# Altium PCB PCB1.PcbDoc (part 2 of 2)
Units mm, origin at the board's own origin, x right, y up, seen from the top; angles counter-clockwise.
Board outline 100 x 72 mm, 4 copper layers (Top Layer, Ground, Power, Bottom Layer), stack 1.562 mm thick; 122 components, 105 nets, 454 pads, 324 vias.
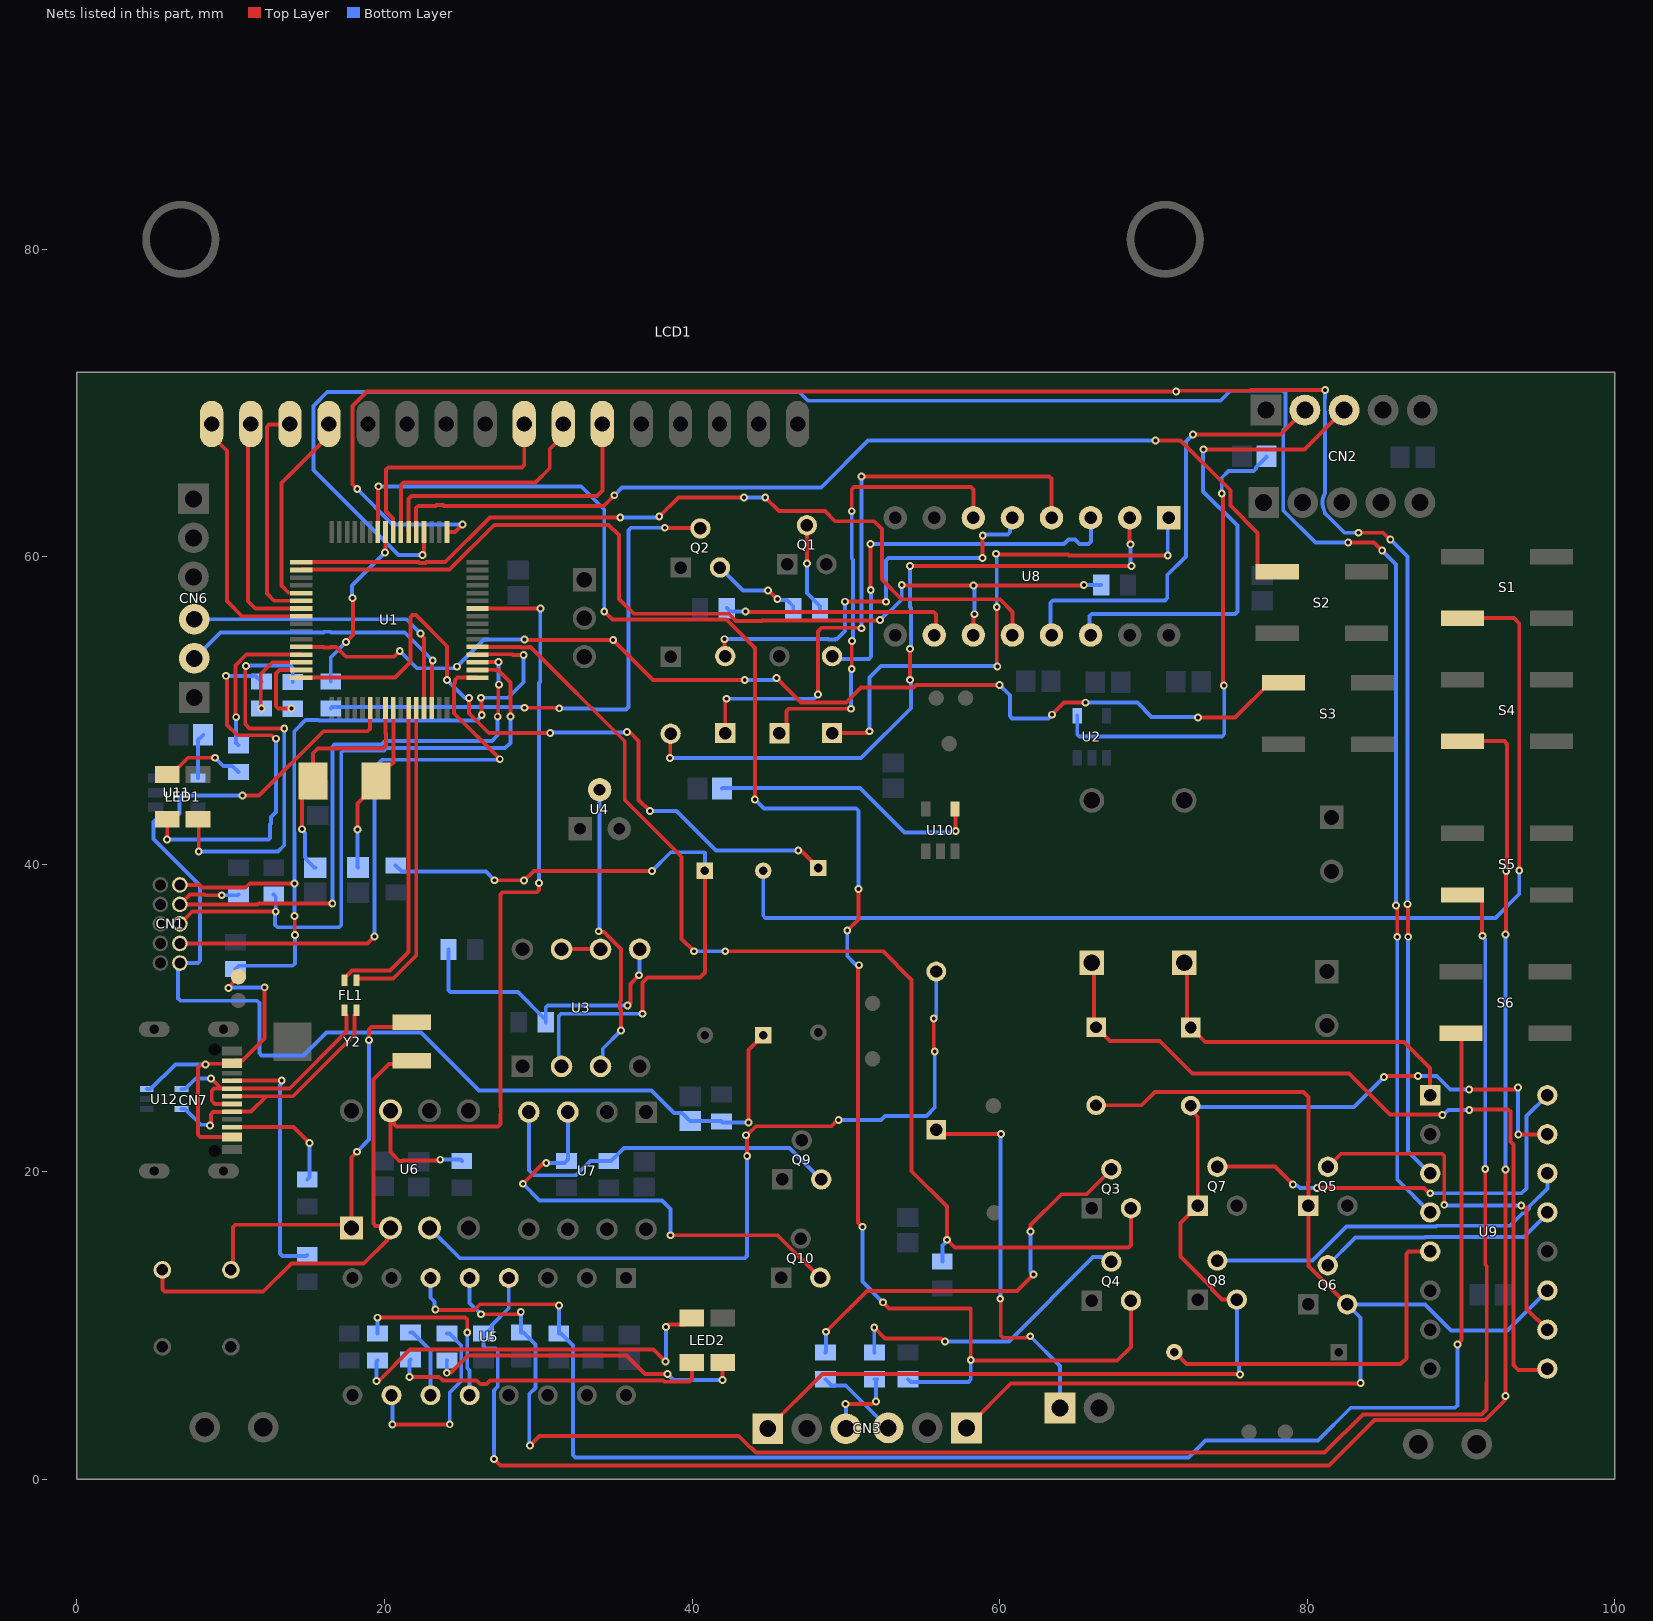
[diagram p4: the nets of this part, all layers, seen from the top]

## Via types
v1: diameter 0.508, hole 0.254, Top Layer to Bottom Layer, tented both sides, 324 vias

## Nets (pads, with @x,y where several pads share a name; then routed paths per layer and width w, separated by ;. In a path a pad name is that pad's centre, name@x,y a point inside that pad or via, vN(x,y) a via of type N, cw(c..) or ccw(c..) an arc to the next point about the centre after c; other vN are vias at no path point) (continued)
M0PWM0: U1.1 U9.3 | length 133.6
  Top Layer w0.254: v1(18.234,64.392) 17.92,64.705 17.92,69.797 18.861,70.738 v1(71.483,70.738) 71.53,70.786 76.297,70.786 76.355,70.843 v1(81.171,70.843) ; U1.1@24.07,61.605 24.591,61.605 v1(25.081,62.095) ; v1(83.339,61.551) 84.943,61.551 85.376,61.118 v1(85.408,61.118) ; v1(86.527,37.401) 86.568,37.36 v1(86.568,35.276)
  Bottom Layer w0.254: v1(18.234,64.392) 20.53,62.095 v1(25.081,62.095) ; v1(81.171,70.843) 81.144,69.559 ccw(c82.398,69.532) 81.171,69.273 81.171,64.151 ccw(c82.25,63.512) 81.075,63.072 81.171,62.817 81.239,62.749 82.437,61.551 v1(83.339,61.551) ; v1(85.408,61.118) 86.527,59.999 v1(86.527,37.401) ; v1(86.568,35.276) 86.568,21.329 U9.3@88,19.897
M0PWM1: U1.4 U9.4 | length 138.7
  Top Layer w0.254: v1(22.476,60.103) 22.476,60.171 22.57,60.265 U1.4@22.57,61.605 ; v1(82.668,60.918) 84.35,60.918 v1(84.878,60.39) ; v1(85.777,37.318) 85.86,37.235 v1(85.86,35.276)
  Bottom Layer w0.254: v1(22.476,60.103) 20.922,60.103 15.38,65.644 15.38,69.797 16.283,70.7 46.974,70.7 47.536,70.138 74.373,70.138 75.021,70.786 78.423,70.786 78.579,70.63 78.579,68.374 78.446,68.241 78.446,63.002 80.53,60.918 v1(82.668,60.918) ; v1(84.878,60.39) 85.777,59.491 v1(85.777,37.318) ; v1(85.86,35.276) 85.86,19.497 U9.4@88,17.357
MOTOR+: C14.2 CN3.1 Q5.1 Q6.3 U9.11 | length 76
  Top Layer w0.254: CN3.1@57.84,3.345 60.728,6.232 83.456,6.232 v1(83.479,6.255) ; C14.2@66.275,24.324 69.239,24.324 70.104,25.189 79.757,25.189 80.08,24.866 80.08,19.326 80.064,19.31 80.064,18.889 80.08,18.873 Q5.1@80.08,17.791 80.08,13.882 82.584,11.379 Q6.3@82.607,11.379
  Bottom Layer w0.254: v1(83.479,6.255) 83.479,10.507 Q6.3@82.607,11.379 87.651,11.379 89.355,9.675 93.018,9.675 U9.11@95.62,12.277
MOTOR-: C15.2 CN3.6 Q7.1 Q8.3 U9.15 | length 80
  Top Layer w0.254: CN3.6@44.926,3.297 48.483,6.854 75.597,6.854 v1(75.624,6.826) ; C15.2@72.424,24.3 72.424,24.025 72.888,23.562 Q7.1@72.888,17.791 71.772,16.675 71.772,14.481 73.802,12.451 73.802,12.35 74.466,11.685 Q8.3@75.428,11.685 ; v1(85,26.162) 85.119,26.162 85.19,26.233 v1(87.21,26.233) ; v1(90.535,25.354) 93.517,25.354 93.647,25.484 v1(93.715,25.484) ; v1(93.729,22.418) 93.739,22.428 95.611,22.428 U9.15@95.62,22.437
  Bottom Layer w0.254: C15.2@72.424,24.3 72.511,24.214 83.052,24.214 v1(85,26.162) ; Q8.3@75.428,11.685 75.428,7.588 75.576,7.44 75.576,6.875 v1(75.624,6.826) ; v1(87.21,26.233) 88.424,26.233 89.303,25.354 v1(90.535,25.354) ; v1(93.715,25.484) 93.722,25.477 93.722,22.425 v1(93.729,22.418)
NetB1_1: B1.1 D3.1 | length 24.9
  Top Layer w0.254: D3.1@55.88,22.733 56.155,22.458 v1(60.095,22.458) ; v1(60.044,11.742) 60.074,11.712 60.074,9.353 60.222,9.205 61.715,9.205 61.764,9.254 61.942,9.254 v1(61.991,9.303)
  Bottom Layer w0.254: v1(60.044,11.742) 60.07,11.767 60.07,22.432 v1(60.095,22.458) ; v1(61.991,9.303) 63.928,7.365 B1.1@63.928,4.646
NetC3_1: C3.1 CN1.10 R6.1 R7.1 U1.38 | length 82.2
  Top Layer w0.254: v1(10.779,44.468) 11.848,44.468 16.026,48.646 18.898,48.646 19.047,48.794 19.047,50.132 U1.38@19.07,50.155 ; v1(43.676,23.206) 43.676,27.924 R7.1@44.63,28.877
  Bottom Layer w0.254: v1(10.779,44.468) 6.813,44.468 6.665,44.319 6.665,43.296 6.516,43.148 5.382,43.148 4.98,42.746 4.98,41.644 8.015,38.609 8.015,33.724 7.866,33.575 CN1.10@6.702,33.575 6.585,33.458 6.585,31.27 6.734,31.121 11.717,31.121 11.866,30.972 11.866,27.72 12.014,27.571 14.739,27.571 16.232,29.064 22.366,29.064 26.151,25.279 37.366,25.279 38.82,23.825 39.356,23.825 C3.1@39.879,23.302 41.883,23.302 R6.1@41.914,23.272 41.98,23.206 v1(43.676,23.206)
NetC4_1: C4.1 U1.41 Y1.2 | length 11.4
  Top Layer w0.254: v1(18.247,42.26) 18.247,43.95 19.45,45.153 Y1.2@19.45,45.403 19.45,45.653 20.273,46.476 20.43,46.476 20.579,46.625 20.579,50.146 U1.41@20.57,50.155
  Bottom Layer w0.254: v1(18.247,42.26) 18.247,39.815 C4.1@18.276,39.786
NetC5_1: C5.1 U1.40 Y1.1 | length 15.5
  Top Layer w0.254: v1(14.64,42.277) 14.64,44.693 Y1.1@15.35,45.403 15.35,47.212 15.66,47.522 19.921,47.522 20.098,47.698 20.098,48.502 20.07,48.53 U1.40@20.07,50.155
  Bottom Layer w0.254: v1(14.64,42.277) 14.64,42.208 14.831,42.018 14.831,40.468 14.905,40.393 14.905,40.319 15.453,39.771 C5.1@15.503,39.771
NetC7_1: C7.1 U2.4 | length 31.2
  Top Layer w0.254: v1@74.496,64.103 74.538,64.061 74.538,51.654 v1(74.58,51.613)
  Bottom Layer w0.254: U2.4@65.05,49.661 65.05,48.444 65.199,48.295 74.457,48.295 74.61,48.448 74.61,51.582 v1(74.58,51.613) ; v1(74.448,64.103) 74.448,65.129 74.887,65.567 76.521,65.567 76.67,65.716 76.67,65.8 76.819,65.948 76.843,65.948 77.366,66.471 C7.1@77.366,66.521
NetC14_1: C14.1 D1.K U9.9 | length 52.8
  Top Layer w0.254: D1.K@66,33.598 66.144,33.454 66.144,29.535 67.172,28.508 70.412,28.508 72.528,26.392 82.726,26.392 85.395,23.722 88.759,23.722 v1(88.789,23.692) ; v1(90.539,24.008) 90.588,24.057 91.122,24.057 91.124,24.06 93.072,24.06 93.221,23.911 93.221,21.957 93.404,21.774 93.404,7.435 93.727,7.112 95.535,7.112 U9.9@95.62,7.197
  Bottom Layer w0.254: v1(88.789,23.692) 88.858,23.692 89.174,24.008 v1(90.539,24.008)
NetC15_1: C15.1 D2.K U9.1 | length 22.8
  Top Layer w0.254: D2.K@72,33.598 72.184,33.414 72.184,29.621 C15.1@72.424,29.38 73.373,28.431 86.307,28.431 88,26.739 U9.1@88,24.977
NetC18_1: C18.1 U10.4 | length 17.9
  Top Layer w0.254: U10.4@57.103,43.591 57.125,43.569 57.125,42.182 v1(57.146,42.161)
  Bottom Layer w0.254: C18.1@41.953,44.922 41.995,44.965 50.925,44.965 53.819,42.07 57.056,42.07 v1(57.146,42.161)
NetC21_1: C21.1 U8.1 | length 35.7
  Top Layer w0.254: C21.1@49.104,48.528 51.413,48.528 v1(51.532,48.647) ; v1(59.761,60.187) 59.81,60.139 59.989,60.139 60.003,60.125 64.457,60.125 64.509,60.074 v1(70.934,60.074) ; v1(59.812,56.718) 59.812,52.888 v1(59.851,52.849)
  Bottom Layer w0.254: v1(51.532,48.647) 51.532,52.138 52.282,52.888 59.799,52.888 59.838,52.849 v1(59.851,52.849) ; v1(59.761,60.187) 59.812,60.136 v1(59.812,56.718) ; v1(70.934,60.074) 70.934,62.459 U8.1@70.996,62.522
NetC21_2: C21.2 U8.3 | length 26.2
  Top Layer w0.254: v1(51.606,60.825) 51.613,60.817 51.613,57.829 v1(51.62,57.822)
  Bottom Layer w0.254: C21.2@49.104,53.528 49.292,53.34 51.501,53.34 51.65,53.489 51.65,57.793 v1(51.62,57.822) ; v1(51.606,60.825) 64.196,60.824 64.485,61.114 64.906,61.114 65.195,60.824 65.77,60.824 65.938,60.993 65.938,62.5 U8.3@65.916,62.522
NetC22_1: C22.1 U8.4 | length 40.2
  Top Layer w0.254: C22.1@42.158,48.528 42.158,50.685 v1(42.232,50.759) ; v1(48.186,51.027) 48.186,55.142 48.42,55.376 50.985,55.376 v1(51.02,55.342) ; v1(51.02,65.219) 63.215,65.219 63.363,65.07 63.363,62.535 U8.4@63.376,62.522
  Bottom Layer w0.254: v1(42.232,50.759) 47.918,50.759 v1(48.186,51.027) ; v1(51.02,55.342) v1(51.02,65.219)
NetC22_2: C22.2 U8.5 | length 27.2
  Top Layer w0.254: v1(42.103,54.631) 42.103,53.583 C22.2@42.158,53.528 ; v1(49.949,57.07) 52.604,57.07 v1(52.61,57.064) ; v1(58.885,59.906) 58.885,61.353 v1(58.904,61.372)
  Bottom Layer w0.254: v1(42.103,54.631) 48.849,54.631 48.876,54.605 49.297,54.605 49.323,54.631 49.428,54.631 49.949,55.152 v1(49.949,57.07) ; v1(52.61,57.064) 52.61,59.753 52.763,59.906 v1(58.885,59.906) ; v1(58.904,61.372) 58.973,61.372 59.036,61.435 60.517,61.435 60.666,61.584 60.666,62.351 U8.5@60.836,62.522
NetC23_2: C23.2 U8.2 | length 45.5
  Top Layer w0.254: v1(38.565,46.898) 38.585,46.918 38.585,48.465 C23.2@38.606,48.486 ; v1(54.166,54.005) 54.174,53.997 54.174,51.999 v1(54.182,51.99) ; v1(54.166,59.391) v1(68.568,59.391) ; U8.2@68.456,62.522 68.456,60.849 v1(68.506,60.8)
  Bottom Layer w0.254: v1(38.565,46.898) 50.988,46.898 54.228,50.138 54.228,51.944 v1(54.182,51.99) ; v1(54.166,54.005) 54.232,54.072 54.232,56.664 54.166,56.73 v1(54.166,59.391) ; v1(68.506,60.8) 68.506,59.453 v1(68.568,59.391)
NetC24_1: C24.1 U8.6 | length 30.1
  Top Layer w0.254: C24.1@45.683,48.51 46.138,48.965 46.138,49.957 46.286,50.106 v1(50.337,50.106) ; v1(50.383,52.7) 50.383,54.491 v1(50.399,54.506) ; v1(50.388,62.955) 50.388,64.366 50.536,64.515 58.148,64.515 58.296,64.366 U8.6@58.296,62.522
  Bottom Layer w0.254: v1(50.337,50.106) 50.337,52.653 v1(50.383,52.7) ; v1(50.388,62.955) 50.388,59.869 50.457,59.8 50.457,54.633 50.399,54.575 v1(50.399,54.506)
NetC26_1: C26.1 U11.4 | length 2.9
  Bottom Layer w0.254: U11.4@7.877,45.602 7.877,48.07 C26.1@8.215,48.409
NetC28_1: C28.1 U6.2 Y2.1 | length 31.8
  Top Layer w0.254: C28.1@5.56,13.617 5.56,12.35 5.709,12.202 12.117,12.202 13.944,14.029 18.656,14.029 20.153,15.525 20.153,16.107 U6.2@20.391,16.346 20.264,16.472 19.427,16.472 19.278,16.621 19.278,25.992 20.289,27.003 21.564,27.003 Y2.1@21.771,27.211
NetC29_1: C29.1 U6.1 Y2.2 | length 27
  Top Layer w0.254: C29.1@10.019,13.617 10.16,13.758 10.16,16.406 10.309,16.554 17.642,16.554 U6.1@17.851,16.346 17.851,20.946 v1(18.207,21.301) ; v1(18.99,28.556) 18.99,29.256 19.139,29.405 21.466,29.405 Y2.2@21.771,29.711
  Bottom Layer w0.254: v1(18.207,21.301) 18.99,22.085 v1(18.99,28.556)
NetCN1_2: CN1.2 R5.1 U1.52 | length 48.6
  Top Layer w0.254: CN1.2@6.702,38.655 7.972,38.655 8.144,38.483 9.208,38.483 9.212,38.486 10.982,38.486 11.242,38.746 v1(14.146,38.746) ; v1(14.146,36.629) 14.164,36.611 14.164,35.413 v1(14.183,35.394) ; U1.52@26.045,53.63 26.068,53.653 28.29,53.653 28.349,53.594 v1(29.052,53.594) ; v1(26.284,50.822) 26.305,50.801 26.305,49.728 v1(26.326,49.707)
  Bottom Layer w0.254: R5.1@10.318,33.175 10.538,33.395 14.034,33.395 14.183,33.544 v1(14.183,35.394) ; v1(14.146,36.629) v1(14.146,38.746) 14.146,42.053 14.132,42.066 14.132,48.627 14.878,49.372 15.703,49.372 15.729,49.346 26.024,49.346 26.326,49.648 v1(26.326,49.707) ; v1(26.284,50.822) 28.042,50.822 29.052,51.832 v1(29.052,53.594)
NetCN1_4: CN1.4 R4.2 U1.51 | length 41.5
  Top Layer w0.254: v1(9.422,37.978) 8.348,37.978 8.293,38.033 7.35,38.033 CN1.4@6.702,37.385 11.747,37.385 11.799,37.436 v1(16.609,37.436) ; U1.51@26.045,53.13 26.052,53.137 27.406,53.137 v1(27.413,53.145) ; v1(27.361,49.593) 27.401,49.633 27.401,51.632 v1(27.441,51.672)
  Bottom Layer w0.254: v1(9.422,37.978) 10.462,37.978 R4.2@10.502,38.018 ; v1(16.609,37.436) 16.609,47.635 16.758,47.784 19.801,47.784 20.026,48.01 26.987,48.01 27.361,48.384 v1(27.361,49.593) ; v1(27.413,53.145) 27.427,53.131 27.427,51.686 v1(27.441,51.672)
NetCN1_6: CN1.6 R3.2 U1.50 | length 41.9
  Top Layer w0.254: CN1.6@6.702,36.115 7.5,36.913 v1(12.932,36.913) ; U1.50@26.061,52.646 27.194,52.646 27.203,52.637 27.372,52.637 28.191,51.818 v1(28.191,49.6)
  Bottom Layer w0.254: R3.2@12.797,38.018 12.932,37.883 v1(12.932,36.913) ; v1@12.888,36.913 12.888,36.051 13.037,35.902 17.041,35.902 17.189,36.051 17.189,47.254 17.338,47.403 19.958,47.403 20.101,47.546 27.844,47.546 28.191,47.893 v1(28.191,49.6)
NetCN1_8: CN1.8 U1.49 | length 40.1
  Top Layer w0.254: CN1.8@6.702,34.845 18.91,34.845 v1(19.36,35.295) ; U1.49@26.045,52.13 24.733,52.13 24.585,51.981 24.585,51.767 24.534,51.717 24.534,49.816 27.502,46.848 v1(27.502,46.829)
  Bottom Layer w0.254: v1(19.36,35.295) 19.357,35.298 19.357,46.313 19.836,46.793 27.466,46.793 v1(27.502,46.829)
NetCN2_2: CN2.2 U8.13 | length 29.1
  Top Layer w0.254: v1(72.569,67.95) 78.276,67.95 CN2.2@79.858,69.532
  Bottom Layer w0.254: U8.13@63.376,54.902 63.305,54.973 63.305,57 63.454,57.149 70.755,57.149 70.904,57.298 70.904,58.797 72.118,60.011 72.118,67.498 v1(72.569,67.95)
NetCN2_3: CN2.3 U8.14 | length 32.7
  Top Layer w0.254: v1(73.249,66.976) 73.27,66.956 79.822,66.956 CN2.3@82.398,69.532
  Bottom Layer w0.254: U8.14@65.916,54.902 65.845,54.973 65.845,56.132 65.993,56.281 75.309,56.281 75.458,56.43 75.458,62.013 73.225,64.246 73.225,66.952 v1(73.249,66.976)
NetCN3_3: CN3.3 R22.1 | length 5.4
  Bottom Layer w0.254: R22.1@48.672,6.508 49.07,6.11 49.996,6.11 CN3.3@52.76,3.345
NetCN3_4: CN3.4 R23.1 | length 5.3
  Top Layer w0.254: v1(49.975,4.889) 51.721,4.889 51.89,5.059 v1(51.959,5.059)
  Bottom Layer w0.254: v1(49.975,4.889) 50.006,4.859 CN3.4@50.006,3.297 ; R23.1@51.872,6.508 52.022,6.508 51.959,6.445 v1(51.959,5.059)
NetCN7_A5: CN7.A5 R37.2 | length 16.4
  Top Layer w0.254: CN7.A5@10.092,25.907 10.115,25.93 10.736,25.93 10.738,25.931 13.32,25.931 v1(13.322,25.93)
  Bottom Layer w0.254: v1(13.322,25.93) 13.273,25.881 13.273,25.715 13.212,25.654 13.212,14.678 13.361,14.53 14.912,14.53 R37.2@14.979,14.597
NetCN7_B5: CN7.B5 R36.2 | length 7.9
  Top Layer w0.254: CN7.B5@10.092,22.907 14.076,22.907 v1(15.121,21.861)
  Bottom Layer w0.254: R36.2@14.979,19.499 15.121,19.641 v1(15.121,21.861)
NetD3_2: D3.2 U6.3 | length 51.4
  Top Layer w0.254: v1(43.586,21.028) 43.586,22.31 v1(43.516,22.38) 43.569,22.38 44.148,22.959 49.058,22.959 49.467,23.369 v1(49.536,23.369) ; v1(55.716,29.97) 55.716,27.89 v1(55.785,27.821)
  Bottom Layer w0.254: U6.3@22.931,16.346 24.903,14.374 43.437,14.374 43.586,14.522 v1(43.586,21.028) ; v1(49.536,23.369) 52.289,23.369 52.554,23.635 55.238,23.635 55.785,24.182 v1(55.785,27.821) ; v1(55.716,29.97) 55.88,30.134 D3.2@55.88,33.02
NetLCD1_4: LCD1.4 U1.6 | length 19.3
  Top Layer w0.254: U1.6@21.561,61.614 21.561,63.753 21.763,63.955 33.82,63.955 34.168,64.303 LCD1.4@34.168,68.626
NetLCD1_5: LCD1.5 U1.7 | length 16.4
  Top Layer w0.254: U1.7@21.072,61.607 21.072,64.665 21.221,64.814 29.817,64.814 30.75,65.746 30.75,66.993 31.628,67.872 LCD1.5@31.628,68.626
NetLCD1_6: LCD1.6 U1.8 | length 16
  Top Layer w0.254: U1.8@20.57,61.605 20.549,61.626 20.549,62.49 20.111,62.929 20.111,65.658 20.26,65.807 28.939,65.807 29.088,65.956 LCD1.6@29.088,68.626
NetLCD1_11: LCD1.11 U1.21 | length 13.3
  Top Layer w0.254: U1.21@14.595,57.63 14.572,57.653 13.755,57.653 13.299,58.109 13.299,64.783 16.388,67.872 LCD1.11@16.388,68.626
NetLCD1_12: LCD1.12 U1.22 | length 14.9
  Top Layer w0.254: LCD1.12@13.848,68.626 13.814,68.592 12.504,68.592 12.356,68.443 12.356,57.591 12.817,57.13 U1.22@14.595,57.13
NetLCD1_13: LCD1.13 U1.23 | length 15.3
  Top Layer w0.254: LCD1.13@11.308,68.626 11.131,68.449 11.131,57.099 11.6,56.63 U1.23@14.595,56.63
NetLCD1_14: LCD1.14 U1.24 | length 17.2
  Top Layer w0.254: LCD1.14@8.768,68.626 8.768,67.872 9.754,66.886 9.754,57.116 10.746,56.125 U1.24@14.59,56.125
NetLED1_1: LED1.1 R11.2 | length 5.5
  Top Layer w0.254: LED1.1@5.877,45.825 6.127,45.825 7.221,46.919 v1(8.98,46.919)
  Bottom Layer w0.254: v1(8.98,46.919) 9.515,46.385 10.104,46.385 R11.2@10.502,45.987
NetLED1_2: LED1.2 R34.2 | length 23.9
  Top Layer w0.254: v1(5.86,41.607) 5.877,41.624 LED1.2@5.877,42.925 ; v1(9.7,52.25) 9.749,52.201 9.749,52.021 9.761,52.01 9.761,49.058 10.435,48.384 12.666,48.384 12.887,48.163 v1(12.942,48.163)
  Bottom Layer w0.254: v1(5.86,41.607) 12.454,41.607 12.556,41.708 12.556,42.592 12.616,42.653 12.616,43.073 12.942,43.399 v1(12.942,48.163) ; v1(9.7,52.25) 11.625,52.25 R34.2@12,51.875
NetLED1_3: LED1.3 R33.2 | length 25.9
  Top Layer w0.254: LED1.3@7.877,42.925 7.924,42.878 v1(7.924,40.829) ; v1(10.989,52.888) 10.946,52.845 10.946,49.107 11.226,48.827 v1(13.485,48.827)
  Bottom Layer w0.254: v1(7.924,40.829) 13.081,40.829 13.486,41.235 13.486,48.826 v1(13.485,48.827) ; v1(10.989,52.888) 11.01,52.909 13.885,52.909 14.034,52.76 R33.2@14.034,51.854
NetLED2_1: LED2.1 R12.2 | length 25.5
  Top Layer w0.254: v1(19.481,6.403) 19.523,6.445 19.67,6.445 21.671,8.447 37.483,8.447 v1(38.267,7.662) ; v1(38.309,9.908) 38.465,10.064 39.564,10.064 LED2.1@39.987,10.487
  Bottom Layer w0.254: v1(19.481,6.403) 19.481,7.674 R12.2@19.541,7.734 ; v1(38.267,7.662) 38.309,7.704 v1(38.309,9.908)
NetLED2_2: LED2.2 R13.2 | length 21
  Top Layer w0.254: v1(21.62,6.653) 23.56,6.653 23.797,6.417 26.001,6.417 26.227,6.192 26.648,6.192 26.873,6.417 38.127,6.417 38.201,6.343 38.622,6.343 38.633,6.354 39.838,6.354 39.987,6.503 LED2.2@39.987,7.587
  Bottom Layer w0.254: v1(21.62,6.653) 21.62,7.735 R13.2@21.686,7.801
NetLED2_3: LED2.3 R14.2 | length 21
  Top Layer w0.254: v1(24.051,6.925) 24.1,6.974 24.35,6.974 25.42,8.043 35.737,8.043 36.929,6.851 v1(38.411,6.851) ; v1(41.984,6.466) 41.987,6.469 LED2.3@41.987,7.587
  Bottom Layer w0.254: v1(24.051,6.925) 24.051,7.72 R14.2@24.067,7.736 ; v1(38.411,6.851) 38.796,6.466 v1(41.984,6.466)
NetQ1_2: Q1.2 R9.2 | length 5.8
  Top Layer w0.254: Q1.2@47.47,62.045 47.473,62.041 47.473,59.551 v1(47.476,59.548)
  Bottom Layer w0.254: v1(47.476,59.548) 47.476,57.63 48.331,56.775 R9.2@48.331,56.625
NetQ2_2: Q2.2 R10.2 | length 35.8
  Top Layer w0.254: v1(29.111,50.174) 31.329,50.174 v1(31.367,50.136) ; v1(38.231,61.88) 38.255,61.856 40.523,61.856 Q2.2@40.546,61.832
  Bottom Layer w0.254: R10.2@16.509,50.125 16.599,50.215 29.069,50.215 v1(29.111,50.174) ; v1(31.367,50.136) 33.538,50.136 33.609,50.065 35.711,50.065 35.86,50.214 35.86,61.707 36.032,61.88 v1(38.231,61.88)
NetQ2_3: Q2.3 R9.1 | length 6
  Top Layer w0.254: v1(44.947,57.79) 44.975,57.79 45.518,57.246 v1(45.546,57.246)
  Bottom Layer w0.254: Q2.3@41.816,59.292 43.319,57.79 v1(44.947,57.79) ; v1(45.546,57.246) 45.615,57.246 45.688,57.173 46.183,57.173 46.581,56.775 R9.1@46.581,56.625
NetQ3_2: Q3.2 R22.2 | length 26.4
  Top Layer w0.254: v1(48.719,9.598) 51.371,12.25 61.135,12.25 v1(62.198,13.313) ; v1(62.007,16.108) 62.007,16.529 64.017,18.539 65.644,18.539 Q3.2@67.27,20.165
  Bottom Layer w0.254: R22.2@48.672,8.258 48.719,8.305 v1(48.719,9.598) ; v1(62.007,16.108) 62.007,13.504 v1(62.198,13.313)
NetQ4_2: Q4.2 R23.2 | length 19.8
  Top Layer w0.254: v1(51.851,9.872) 52.561,9.162 56.181,9.162 56.371,8.972 v1(56.44,8.972)
  Bottom Layer w0.254: v1(51.851,9.872) 51.851,8.278 R23.2@51.872,8.258 ; v1(56.44,8.972) 60.598,8.972 66.087,14.46 66.681,14.46 66.981,14.16 Q4.2@67.27,14.16
NetQ5_1: 
NetQ5_2: Q5.2 U9.10 | length 25.1
  Top Layer w0.254: Q5.2@81.35,20.331 82.188,21.169 88.768,21.169 88.917,21.02 v1(88.917,17.851) ; v1(93.922,17.812) 93.991,17.812 94.139,17.663 94.273,17.663 94.273,11.084 U9.10@95.62,9.737
  Bottom Layer w0.254: v1(88.917,17.851) 88.959,17.851 88.999,17.812 v1(93.922,17.812)
NetQ6_1: 
NetQ6_2: Q6.2 U9.13 | length 15.8
  Bottom Layer w0.254: Q6.2@81.337,13.919 83.149,15.731 87.668,15.731 87.691,15.754 94.095,15.754 95.62,17.28 U9.13@95.62,17.357
NetQ7_1: 
NetQ7_2: Q7.2 U9.16 | length 27.6
  Top Layer w0.254: Q7.2@74.158,20.331 77.903,20.331 v1(79.068,19.165) ; v1(80.634,18.937) 87.597,18.937 87.934,18.6 v1(88.002,18.6)
  Bottom Layer w0.254: v1(79.068,19.165) 79.117,19.116 79.357,19.116 79.536,18.937 v1(80.634,18.937) ; v1(88.002,18.6) 93.943,18.6 94.261,18.918 94.261,23.618 U9.16@95.62,24.977
NetQ8_1: 
NetQ8_2: Q8.2 U9.14 | length 24.5
  Bottom Layer w0.254: Q8.2@74.158,14.225 80.35,14.225 82.569,16.444 87.62,16.444 87.621,16.443 88.379,16.443 88.426,16.49 93.194,16.49 94.008,17.304 94.132,17.304 94.43,17.602 94.43,17.726 95.62,18.916 U9.14@95.62,19.897
NetQ9_3: Q9.3 R25.1 U7.4 | length 24.5
  Bottom Layer w0.254: U7.4@29.388,23.881 29.388,20.098 29.713,19.774 32.463,19.774 33.397,20.707 R25.1@34.586,20.707 34.736,20.707 35.565,21.536 46.35,21.536 48.382,19.505 Q9.3@48.405,19.505
NetQ10_3: Q10.3 R24.1 U7.3 | length 29.5
  Top Layer w0.254: v1(28.998,19.222) 30.346,20.57 v1(30.522,20.57) ; v1(38.606,15.869) 45.562,15.869 48.317,13.115 Q10.3@48.34,13.115
  Bottom Layer w0.254: v1(28.998,19.222) 30.092,18.128 38.057,18.128 38.606,17.58 v1(38.606,15.869) ; v1(30.522,20.57) 31.701,20.57 R24.1@31.838,20.707 31.928,20.798 U7.3@31.928,23.881
NetR1_1: R1.1 R2.2 U3.2 | length 44.3
  Top Layer w0.254: v1(27.163,38.958) 29.056,38.958 v1(29.081,38.934) 29.713,39.566 v1(37.406,39.566) ; v1(36.787,30.276) 36.787,32.298 37.113,32.623 40.512,32.623 40.838,32.949 R1.1@40.838,39.577
  Bottom Layer w0.254: R2.2@20.73,39.914 21.128,39.516 26.606,39.516 v1(27.163,38.958) ; U3.2@31.513,26.853 31.334,27.032 31.334,30.127 31.483,30.276 v1(36.787,30.276) ; v1(37.406,39.566) 38.617,40.777 40.781,40.777 40.838,40.72 R1.1@40.838,39.577
NetR7_2: R7.2 S1.2 | length 74.2
  Top Layer w0.254: S1.2@90.1,56 93.439,56 93.793,55.645 v1(93.793,39.581)
  Bottom Layer w0.254: R7.2@44.63,39.577 44.63,36.649 44.779,36.5 92.241,36.5 93.793,38.053 v1(93.793,39.581)
NetR8_1: R8.1 U1.32 | length 48
  Top Layer w0.254: U1.32@14.595,52.13 14.618,52.153 20.676,52.153 21.681,53.158 21.681,56.058 21.829,56.207 22.04,56.207 24.077,54.17 v1(24.077,51.977) ; v1(25.499,50.807) 25.499,49.816 26.781,48.534 v1(30.777,48.534) ; v1(35.763,48.588) 35.812,48.539 36.015,48.539 36.532,48.023 36.532,44.184 v1(37.264,43.451) ; v1(46.906,40.888) 47.081,40.888 R8.1@48.214,39.755
  Bottom Layer w0.254: v1(24.077,51.977) 25.247,50.807 v1(25.499,50.807) ; v1(30.777,48.534) 30.804,48.561 35.736,48.561 v1(35.763,48.588) ; v1(37.264,43.451) 38.999,43.451 41.562,40.888 v1(46.906,40.888)
NetR10_1: R10.1 U1.9 | length 11.3
  Top Layer w0.254: v1(17.499,54.44) 17.956,54.897 17.956,57.276 v1(17.919,57.313) ; v1(20.041,60.265) 20.056,60.279 20.056,61.591 U1.9@20.07,61.605
  Bottom Layer w0.254: R10.1@16.509,51.875 16.509,53.45 v1(17.499,54.44) ; v1(17.919,57.313) 17.899,57.334 17.899,58.122 v1(20.041,60.265)
NetR11_1: R11.1 U1.29 | length 9.8
  Top Layer w0.254: v1(10.357,49.559) 10.315,49.6 10.315,52.932 11.013,53.63 U1.29@14.595,53.63
  Bottom Layer w0.254: v1(10.357,49.559) 10.357,47.882 R11.1@10.502,47.737
NetR12_1: R12.1 U5.12 | length 11.9
  Top Layer w0.254: v1(19.545,10.513) 19.569,10.537 25.235,10.537 25.384,10.388 v1(25.384,9.555)
  Bottom Layer w0.254: R12.1@19.541,9.484 19.545,9.489 v1(19.545,10.513) ; v1(25.384,9.555) 25.384,7.232 25.541,7.075 U5.12@25.541,5.471
NetR13_1: R13.1 U5.11 | length 4.7
  Bottom Layer w0.254: R13.1@21.686,9.551 21.836,9.551 23.001,8.387 U5.11@23.001,5.471
NetR14_1: R14.1 U5.10 | length 12.4
  Top Layer w0.254: v1(20.512,3.556) 24.227,3.556 v1(24.248,3.577)
  Bottom Layer w0.254: U5.10@20.461,5.471 20.512,5.42 v1(20.512,3.556) ; R14.1@24.067,9.486 24.217,9.486 24.996,8.707 24.996,6.402 24.248,5.654 v1(24.248,3.577)
NetR15_1: R15.1 S4.2 U5.4 | length 126.8
  Top Layer w0.254: v1(27.123,1.33) 27.554,0.9 81.429,0.9 84.376,3.847 91.582,3.847 92.842,5.107 92.842,5.361 92.913,5.431 92.902,5.442 92.902,20.144 v1(92.896,20.151) ; S4.2@90.1,48 92.821,48 92.997,47.824 92.997,39.612 v1(92.941,39.556) 92.941,35.465 v1(92.902,35.426)
  Bottom Layer w0.254: v1(27.123,1.33) 27.123,5.788 27.369,6.034 27.369,8.366 27.22,8.515 26.589,8.515 26.44,8.663 R15.1@26.44,9.486 26.59,9.486 26.988,9.884 26.988,10.034 28.081,11.127 U5.4@28.081,13.091 ; v1(92.896,20.151) 92.899,20.154 92.899,35.423 v1(92.902,35.426)
  other v1: 92.891,5.409
NetR16_1: R16.1 S5.2 U5.5 | length 113.4
  Top Layer w0.254: v1(26.27,10.735) 28.725,10.735 v1(28.866,10.876) ; v1(29.459,2.2) 30.082,2.823 43.04,2.823 43.82,2.043 43.866,2.043 44.166,1.743 81.133,1.743 83.618,4.228 91.346,4.228 91.655,4.537 91.655,6.299 91.68,6.324 91.68,13.885 91.583,13.982 v1(91.583,20.179) ; S5.2@90.1,38 91,38 91.373,37.627 91.373,35.377 v1(91.401,35.349)
  Bottom Layer w0.254: U5.5@25.541,13.091 25.541,11.464 v1(26.27,10.735) ; v1(28.866,10.876) 28.866,9.576 R16.1@28.89,9.551 29.04,9.551 29.819,8.772 29.819,5.944 29.414,5.539 29.414,2.244 v1(29.459,2.2) ; v1(91.401,35.349) 91.401,35.28 91.583,35.099 v1(91.583,20.179)
NetR17_1: R17.1 S6.2 U5.6 | length 103.9
  Top Layer w0.254: v1(23.308,11.045) 23.332,11.021 25.837,11.021 26.2,11.384 31.269,11.384 v1(31.349,11.303) ; v1(89.77,8.773) 89.77,8.788 90.031,9.049 90.031,25.14 90.027,25.144 90.027,25.565 90.031,25.568 90.031,28.969 S6.2@90,29
  Bottom Layer w0.254: U5.6@23.001,13.091 23.001,11.807 23.259,11.548 23.259,11.093 v1(23.308,11.045) ; v1(31.349,11.303) 31.349,9.498 R17.1@31.335,9.484 31.485,9.484 32.264,8.705 32.264,5.849 32.259,5.845 32.259,1.572 32.413,1.419 72.278,1.419 73.394,2.535 80.714,2.535 82.835,4.657 89.621,4.657 89.77,4.805 v1(89.77,8.773)
NetR19_2: R19.2 U8.10 | length 15.1
  Top Layer w0.254: v1(43.471,56.434) 43.504,56.402 55.703,56.402 55.851,56.253 55.851,54.997 U8.10@55.756,54.902
  Bottom Layer w0.254: R19.2@42.261,56.65 42.477,56.434 v1(43.471,56.434)
NetR26_2: R26.2 U9.5 | length 24
  Top Layer w0.254: R26.2@71.364,8.276 72.151,7.489 86.076,7.489 86.447,7.86 86.447,14.668 86.596,14.817 U9.5@88,14.817
NetR29_1: R29.1 R30.2 U3.5 | length 20.2
  Top Layer w0.254: v1(35.806,30.82) 35.842,30.82 35.991,30.969 35.991,32.22 v1(36.548,32.777)
  Bottom Layer w0.254: R29.1@24.158,34.45 24.158,31.829 24.307,31.68 28.671,31.68 30.486,29.865 R30.2@30.486,29.715 30.486,30.671 30.635,30.82 v1(35.806,30.82) ; v1(36.548,32.777) 36.593,32.822 U3.5@36.593,34.473
NetR33_1: R33.1 U1.31 | length 4.9
  Top Layer w0.254: v1(13.945,50.121) 13.096,50.121 12.948,50.27 12.948,52.411 13.173,52.636 U1.31@14.589,52.636
NetR34_1: R34.1 U1.30 | length 5.2
  Top Layer w0.254: v1(12,50.125) 11.953,50.172 11.953,52.361 12.722,53.13 U1.30@14.595,53.13
NetS2_1: S2.1 U1.5 | length 64.8
  Top Layer w0.254: U1.5@22.058,61.617 22.058,63.153 22.206,63.302 23.313,63.302 23.374,63.363 23.795,63.363 23.856,63.302 34.258,63.302 v1(34.946,63.99) ; v1(70.147,67.553) 71.764,67.553 75.004,64.313 75.004,63.318 76.782,61.54 76.782,59.388 77.155,59.015 S2.1@78.055,59.015
  Bottom Layer w0.254: v1(34.946,63.99) 35.456,64.5 48.4,64.5 51.453,67.553 v1(70.147,67.553)
NetS3_1: S3.1 U1.28 | length 71.3
  Top Layer w0.254: U1.28@14.595,54.13 16.051,54.13 16.081,54.1 16.502,54.1 16.532,54.13 16.857,54.13 17.5,53.487 17.71,53.487 17.713,53.489 20.611,53.489 v1(20.995,53.873) ; v1(29.116,54.61) 29.152,54.574 v1(34.871,54.574) 37.458,51.987 v1(43.43,51.987) ; v1(45.493,52.102) 47.076,50.519 50.031,50.519 50.995,51.482 54.392,51.482 54.571,51.662 v1(59.991,51.662) ; v1(63.411,49.723) 64.192,50.504 v1(65.592,50.504) ; v1(72.899,49.537) 75.313,49.537 77.566,51.79 S3.1@78.466,51.79
  Bottom Layer w0.254: v1(20.995,53.873) 20.995,53.852 22.104,52.742 24.615,52.742 v1(24.717,52.844) 26.483,54.61 v1(29.116,54.61) ; v1(43.43,51.987) 45.377,51.987 v1(45.493,52.102) ; v1(59.991,51.662) 60.665,50.988 60.665,49.629 60.813,49.481 63.169,49.481 v1(63.411,49.723) ; v1(65.592,50.504) 68.968,50.504 69.89,49.582 72.855,49.582 v1(72.899,49.537)
NetU3_3: U3.3 U4.2 | length 19.4
  Top Layer w0.254: v1(33.931,35.639) 33.979,35.59 34.282,35.59 35.387,34.486 35.387,31.12 35.298,31.031 35.298,30.61 35.387,30.521 v1(35.387,29.192)
  Bottom Layer w0.254: v1(33.931,35.639) 33.99,35.698 U4.2@33.99,44.842 ; U3.3@34.053,26.853 34.196,26.995 34.196,28.001 v1(35.387,29.192)
NetU3_6: U3.6 U3.7 | length 2.5
  Top Layer w0.254: U3.7@31.513,34.473 U3.6@34.053,34.473
PhA: Q3.3 R20.1 U1.53 | length 76.6
  Top Layer w0.254: U1.53@26.045,54.13 28.877,54.13 28.905,54.102 29.326,54.102 29.354,54.13 29.49,54.13 35.622,47.997 35.622,44.187 39.325,40.485 39.325,35.148 v1(40.13,34.342) ; v1(42.158,34.342) 52.41,34.342 54.282,32.471 54.282,20.035 56.587,17.73 v1(56.587,15.578) 57.081,15.084 68.391,15.084 68.54,15.233 Q3.3@68.54,17.625
  Bottom Layer w0.254: v1(40.13,34.342) v1(42.158,34.342) ; R20.1@56.279,14.166 56.279,15.201 56.587,15.51 v1(56.587,15.578)
PhB: Q4.3 R21.1 U1.10 | length 114.5
  Top Layer w0.254: U1.10@19.57,61.605 19.587,61.622 19.587,64.555 v1(19.603,64.572) ; v1(34.294,56.435) 34.824,55.904 42.236,55.904 44.082,54.059 v1(44.082,44.215) ; v1(50.091,35.689) 50.816,36.414 v1(50.816,38.38) ; v1(50.866,33.434) 50.866,33.366 50.782,33.281 50.782,16.713 v1(51.076,16.419) ; v1(52.419,11.511) 52.817,11.113 58.123,11.113 v1(58.123,7.76) 58.165,7.718 67.649,7.718 68.54,8.609 Q4.3@68.54,11.62
  Bottom Layer w0.254: v1(19.603,64.572) 32.795,64.572 34.294,63.072 v1(34.294,56.435) ; v1(44.082,44.215) 44.674,43.623 50.667,43.623 50.816,43.474 v1(50.816,38.38) ; v1(50.091,35.689) 50.091,34.019 50.628,33.483 50.818,33.483 v1(50.866,33.434) ; v1(51.076,16.419) 51.076,12.854 v1(52.419,11.511) ; R21.1@54.052,6.508 54.228,6.332 57.974,6.332 58.123,6.481 v1(58.123,7.76)
PINT: R31.1 U1.58 U6.7 | length 55.7
  Top Layer w0.254: v1(23.628,20.785) 23.579,20.737 23.295,20.737 23.292,20.733 21.199,20.733 21.175,20.709 20.964,20.709 20.391,21.283 U6.7@20.391,23.966 20.617,23.739 20.617,23.101 20.766,22.953 27.391,22.953 27.54,23.101 27.54,23.766 27.562,23.788 27.562,24.209 27.54,24.232 27.54,38.027 27.688,38.175 29.909,38.175 30.058,38.324 v1(30.058,38.781) ; U1.58@26.045,56.63 26.052,56.637 30.136,56.637 v1(30.153,56.62)
  Bottom Layer w0.254: v1(23.628,20.785) 24.956,20.785 R31.1@25.033,20.707 ; v1(30.058,38.781) 30.058,51.775 30.128,51.845 30.128,56.595 v1(30.153,56.62)
RX: U1.17 U8.12 | length 54.6
  Top Layer w0.254: U1.17@14.595,59.63 14.617,59.652 22.208,59.652 22.266,59.595 22.686,59.595 22.744,59.652 23.953,59.652 26.852,62.552 v1(35.334,62.552) ; v1(37.871,62.611) 39.11,63.849 v1(43.388,63.849) ; v1(44.762,63.849) 45.653,62.959 48.652,62.959 49.309,62.302 51.844,62.302 52.355,61.791 52.355,58.532 52.376,58.511 52.376,58.472 53.622,57.226 60.023,57.226 60.836,56.412 U8.12@60.836,54.902
  Bottom Layer w0.254: v1(35.334,62.552) 37.812,62.552 v1(37.871,62.611) ; v1(43.388,63.849) v1(44.762,63.849)
RX1: CN6.3 U1.45 | length 20
  Top Layer w0.254: v1(22.346,55.002) 22.346,54.934 22.57,54.71 22.57,50.173 U1.45@22.579,50.164
  Bottom Layer w0.254: CN6.3@7.631,55.925 21.423,55.925 v1(22.346,55.002)
TX: R18.2 U1.18 U8.11 | length 63
  Top Layer w0.254: U1.18@14.595,59.13 14.618,59.153 15.313,59.153 15.316,59.156 24.231,59.156 27.14,62.064 34.58,62.064 35.246,61.398 35.246,57.254 36.215,56.285 42.394,56.285 42.855,55.824 44.532,55.824 44.557,55.85 52.177,55.85 v1(52.216,55.888) ; v1(53.64,58.147) 53.663,58.147 53.691,58.118 v1(58.31,58.118) 58.325,58.133 65.462,58.133 v1(65.477,58.148) ; U8.11@58.296,54.902 58.296,56.196 v1(58.359,56.258)
  Bottom Layer w0.254: v1(52.216,55.888) 52.733,56.405 52.823,56.405 53.64,57.223 v1(53.64,58.147) ; v1(58.31,58.118) 58.359,58.069 v1(58.359,56.258) ; v1(65.477,58.148) 66.602,58.148 R18.2@66.609,58.155
TX1: CN6.2 U1.46 | length 20.1
  Top Layer w0.254: U1.46@23.07,50.155 23.093,50.178 23.093,53.203 v1(23.14,53.25)
  Bottom Layer w0.254: CN6.2@7.656,53.385 9.342,55.071 16.036,55.071 16.081,55.116 16.502,55.116 16.547,55.071 21.319,55.071 v1(23.14,53.25)
USBD0_N: FL1.2 U1.43 | length 20.9
  Top Layer w0.254: FL1.2@17.393,32.452 17.393,32.627 17.466,32.7 17.507,32.7 17.888,33.081 20.36,33.081 21.56,34.281 U1.43@21.56,50.145
USBD0_P: FL1.1 U1.44 | length 20.7
  Top Layer w0.254: FL1.1@18.193,32.452 18.193,32.5 18.266,32.573 20.571,32.573 22.068,34.071 U1.44@22.068,50.153
USBD1_N: CN7.A7 CN7.B7 FL1.3 U12.4 | length 17
  Top Layer w0.254: v1(8.73,26.062) 9.363,25.43 ; CN7.A7@10.084,24.415 10.076,24.407 8.983,24.407 8.772,24.618 8.772,25.258 8.92,25.407 9.363,25.407 CN7.B7@10.092,25.407 CN7.B7@10.153,25.407 ; CN7.B7@10.153,25.422 13.842,25.422 17.539,29.119 17.539,30.181 17.393,30.327 FL1.3@17.393,30.502
  Bottom Layer w0.254: U12.4@6.792,25.373 7.042,25.373 7.731,26.062 v1(8.73,26.062)
USBD1_P: CN7.A6 CN7.B6 FL1.4 U12.5 | length 17.9
  Top Layer w0.254: v1(8.661,23.008) 8.71,23.057 8.71,23.735 8.859,23.884 9.569,23.884 9.592,23.907 11.329,23.907 12.331,24.908 ; CN7.A6@10.616,24.908 12.331,24.908 ; FL1.4@18.193,30.502 18.193,30.327 18.047,30.181 18.047,28.909 14.046,24.908 12.331,24.908
  Bottom Layer w0.254: U12.5@6.792,24.073 7.042,24.073 8.058,23.057 8.613,23.057 v1(8.661,23.008)
VBUS: CN7.A4B9 CN7.B4A9 TP_VBUS.1 U12.3 | length 22.9
  Top Layer w0.254: v1(8.361,26.985) 8.313,26.936 8.037,26.936 7.88,26.779 7.88,22.406 8.028,22.257 CN7.B4A9@10.092,22.257 ; v1@8.397,27.021 10.057,27.021 CN7.A4B9@10.092,27.057 10.265,27.23 10.775,27.23 12.213,28.668 v1(12.213,31.994) ; v1(9.859,31.954) 9.859,31.995 10.502,32.638 TP_VBUS.1@10.502,32.679
  Bottom Layer w0.254: U12.3@4.542,25.373 4.792,25.373 6.404,26.985 v1(8.361,26.985) ; v1(9.859,31.954) 9.879,31.974 12.193,31.974 v1(12.213,31.994)
pads on no net: B1.2 CN1.1 CN1.7 CN2.1 CN2.4 CN2.6 CN2.7 CN2.8 CN2.9 CN2.10 CN6.1 CN6.6 CN7.0 CN7.A8 CN7.B8 LCD1.7 LCD1.8 LCD1.9 LCD1.10 LCD1.15 LCD1.16 LCD1.S1 LCD1.S2 S1.3 S1.4 S2.3 S2.4 S3.3 S3.4 S4.3 S4.4 S5.3 S5.4 S6.3 S6.4 U1.13 U1.14 U1.15 U1.16 U1.19 U1.20 U1.25 U1.33 U1.34 U1.35 U1.36 U1.56 U1.57 U1.59 U1.60 U1.61 U1.62 U5.7 U5.9 U5.13 U7.8 U8.7 U8.8 U8.9 U12.1 Y2.0

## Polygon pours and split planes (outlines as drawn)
GND on Ground (split plane): 99.49,45.849 60.96,45.849 60.91,45.84 60.868,45.812 60.84,45.77 60.831,45.72 60.831,0.51 0.51,0.51 0.51,71.49 99.49,71.49
GND_12 on Ground (split plane): 99.49,0.51 61.089,0.51 61.089,45.591 99.49,45.591
+5.0V on Power (split plane): 88.771,45.849 60.96,45.849 60.91,45.84 60.868,45.812 60.84,45.77 60.831,45.72 60.831,0.51 3.544,0.51 3.544,5.964 15.111,5.964 15.111,2.54 15.12,2.49 15.148,2.448 15.19,2.42 15.24,2.411 40.499,2.411 40.549,2.42 40.591,2.448 43.093,4.951 58.42,4.951 58.47,4.96 58.512,4.988 58.54,5.03 58.549,5.08 58.549,45.72 58.549,48.131 78.74,48.131 78.79,48.14 78.832,48.168 78.86,48.21 78.869,48.26 78.869,53.34 78.869,55.88 78.86,55.93 78.832,55.972 78.79,56 78.74,56.009 76.254,56.009 74.912,57.351 74.912,64.864 75.959,65.911 81.28,65.911 81.33,65.92 81.372,65.948 83.874,68.451 88.771,68.451
3.3VP on Power (split plane): 99.49,45.849 89.029,45.849 89.029,68.58 89.02,68.63 88.992,68.672 88.95,68.7 88.9,68.709 83.82,68.709 83.77,68.7 83.728,68.672 81.226,66.169 75.905,66.169 75.856,66.16 75.814,66.132 74.691,65.009 74.663,64.967 74.653,64.917 74.653,57.297 74.663,57.248 74.691,57.206 76.108,55.788 76.15,55.76 76.2,55.751 78.611,55.751 78.611,53.34 78.611,48.389 76.329,48.389 76.329,53.34 76.32,53.39 76.292,53.432 76.25,53.46 76.2,53.469 50.8,53.469 50.75,53.46 50.708,53.432 50.68,53.39 50.671,53.34 50.671,50.929 35.689,50.929 35.689,60.96 35.68,61.01 35.652,61.052 35.61,61.08 35.56,61.089 30.48,61.089 30.43,61.08 30.388,61.052 30.36,61.01 30.351,60.96 30.351,38.229 22.86,38.229 22.81,38.22 22.768,38.192 22.74,38.15 22.731,38.1 22.731,33.02 22.74,32.97 22.768,32.928 22.81,32.9 22.86,32.891 38.1,32.891 38.15,32.9 38.192,32.928 38.22,32.97 38.229,33.02 38.229,45.591 50.671,45.591 50.671,22.914 48.206,20.449 30.48,20.449 30.43,20.44 30.388,20.412 30.36,20.37 30.351,20.32 30.351,15.24 30.36,15.19 30.388,15.148 31.697,13.84 31.697,11.353 31.707,11.304 31.735,11.262 34.15,8.847 34.192,8.819 34.242,8.809 47.038,8.809 47.088,8.819 47.13,8.847 53.432,15.148 53.46,15.19 53.469,15.24 53.469,37.971 58.291,37.971 58.291,5.209 43.039,5.209 42.99,5.2 42.948,5.172 40.446,2.669 15.369,2.669 15.369,6.093 15.36,6.143 15.332,6.185 15.29,6.213 15.24,6.223 3.419,6.223 3.37,6.213 3.328,6.185 3.323,6.181 3.295,6.139 3.285,6.089 3.285,0.51 0.51,0.51 0.51,71.49 99.49,71.49
+12V on Power (split plane): 99.49,0.51 61.089,0.51 61.089,45.591 99.49,45.591
+5.0VP on Power (split plane): 58.291,38.229 53.34,38.229 53.29,38.22 53.248,38.192 53.22,38.15 53.211,38.1 53.211,15.294 46.985,9.068 34.295,9.068 31.956,11.407 31.956,13.893 31.946,13.943 31.918,13.985 30.609,15.294 30.609,20.191 48.26,20.191 48.31,20.2 48.352,20.228 50.892,22.768 50.92,22.81 50.929,22.86 50.929,45.591 58.291,45.591
+3.3VA on Power (split plane): 35.431,50.8 35.44,50.75 35.468,50.708 35.51,50.68 35.56,50.671 50.8,50.671 50.85,50.68 50.892,50.708 50.92,50.75 50.929,50.8 50.929,53.211 76.071,53.211 76.071,48.389 58.42,48.389 58.37,48.38 58.328,48.352 58.3,48.31 58.291,48.26 58.291,45.849 38.1,45.849 38.05,45.84 38.008,45.812 37.98,45.77 37.971,45.72 37.971,33.149 22.989,33.149 22.989,37.971 30.48,37.971 30.53,37.98 30.572,38.008 30.6,38.05 30.609,38.1 30.609,60.831 35.431,60.831

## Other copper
Ground (plane layer: these items are gaps in the copper):
  lines w0.254: 60.96,0 60.96,45.72 100.024,45.72
Power (plane layer: these items are gaps in the copper):
  lines w0.254: 3.415,0.317 3.415,6.089 3.419,6.093 15.24,6.093 15.24,2.54 40.499,2.54 43.039,5.08 58.42,5.08 58.42,45.72 ; 50.8,45.72 50.8,22.86 48.26,20.32 30.48,20.32 30.48,15.24 31.827,13.893 31.827,11.353 34.242,8.938 47.038,8.938 53.34,15.24 53.34,38.1 58.42,38.1 ; 60.96,0 60.96,45.72 99.06,45.72 99.639,45.72 ; 88.9,45.72 88.9,68.58 83.82,68.58 81.28,66.04 75.905,66.04 74.783,64.917 74.783,57.297 76.2,55.88 78.74,55.88 78.74,53.34 78.74,48.26 76.2,48.26 ; 58.42,45.72 58.42,48.26 76.2,48.26 ; 58.42,45.72 38.1,45.72 38.1,33.02 22.86,33.02 22.86,38.1 30.48,38.1 30.48,60.96 35.56,60.96 35.56,50.8 50.8,50.8 50.8,53.34 73.66,53.34 76.2,53.34 76.2,48.26

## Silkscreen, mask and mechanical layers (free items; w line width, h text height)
Top Overlay:
  lines w0.254: 3.099,0 3.099,17.78 ; 3.099,30.48 3.099,66.2 3.099,71.28 ; 97.815,1.295 97.815,71.35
